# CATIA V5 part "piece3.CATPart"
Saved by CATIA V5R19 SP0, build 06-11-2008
Part number: piece3
Bounding box of the stored display mesh (mm): x 0 to 20, y -69.639 to 85.036, z -40.124 to 15.859
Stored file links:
  C:\Documents and Settings\Administrateur\Bureau\Bureau\piece3.CATPart
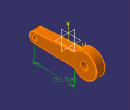
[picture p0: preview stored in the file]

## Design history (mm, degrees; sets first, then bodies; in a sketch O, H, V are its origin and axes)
Sketch1 on yz-plane, origin (0, 0, 0), H (0, 1, 0), V (0, 0, 1)
  point P2 (34.1186, -27.9589)
  arc A1 centre (57.2141, -12.1286) radius 28 from (34.3141, 3.9832) to (34.1186, -27.9589) cw
  point P3 (57.2141, -12.1286)
  line L1 (34.3141, 3.9832) -> (-58.5282, -1.871)
  line L2 (34.1186, -27.9589) -> (-58.0483, -25.8441)
  point P5 (34.1186, -27.9589)
  arc A2 centre (-57.773, -13.8472) radius 12 from (-58.5282, -1.871) to (-58.0483, -25.8441) ccw
  point P7 (-57.773, -13.8472)
  point P8 (-58.0483, -25.8441)
  radius A1 = 28
  radius A2 = 12
  distance P3 P7 = 115
  coincidence: P5 A1, A2 P8, P8 L2, P2 P5
  tangency: L1 A2, L2 A2
Pad1: profile Sketch1, direction (1, 0, 0), length 20
Body1 (main body)
  Sketch2 on yz-plane, origin (0, 0, 0), H (0, 1, 0), V (0, 0, 1)
  Chamfer1: length 1, angle 45, on face of Pad1 from Sketch1.A1; face of Pad1 from Sketch1.L1; end face of Pad1
  Sketch3 on end face of Pad1, origin (20, 64.4285, -12.3595), H (0, 1, 0), V (0, 0, 1)
    point P1 (-7.0221, 0.0098)
  Hole1: placed by Sketch3, at (20, 57.4064, -12.3497) direction (-1, 0, 0), diameter 17, through (limit type 3)
  Sketch4 on end face of Pad1, origin (20, -32.524, -16.8677), H (0, 1, 0), V (0, 0, 1)
    point P1 (-24.2266, 2.5004)
  Hole2: placed by Sketch4, at (20, -56.7506, -14.3673) direction (-1, 0, 0), diameter 10, through (limit type 3)
  Chamfer2: length 1, angle 45, on edge [face of Hole2 | start face of Pad1]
